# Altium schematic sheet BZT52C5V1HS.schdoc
size 127 x 101 mm
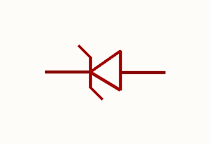
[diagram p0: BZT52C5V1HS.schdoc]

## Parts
D?  bzt52c5v1hs  [SOD-323_L1.8-W1.3-LS2.5-RD]  (value not drawn)

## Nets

Not connected (* = marked no-connect by the designer): D? 1(-) 2(+)

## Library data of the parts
D? = bzt52c5v1hs: 二极管配置:1个独立式;稳压值(标称值):-;稳压值(范围值):5.1V~5.5V;耗散功率(Pd):500mW;; Manufacturer: CJ(江苏长电/长晶); AddInBom: yes; ModelId: db63db13d9e342eb939127d413d6200b; ModelTransform: 104.3305,51.181,0,0,0,0,0,-0.004,0; Diode Configuration: 1个独立式; Reverse Leakage Current (Ir): 50uA@4.2V; Pd - Power Dissipation: 500mW; Impedance(Zzt): 50Ω; Impedance(Zzk): 450Ω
